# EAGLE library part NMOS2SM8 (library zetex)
Dual MOS FET
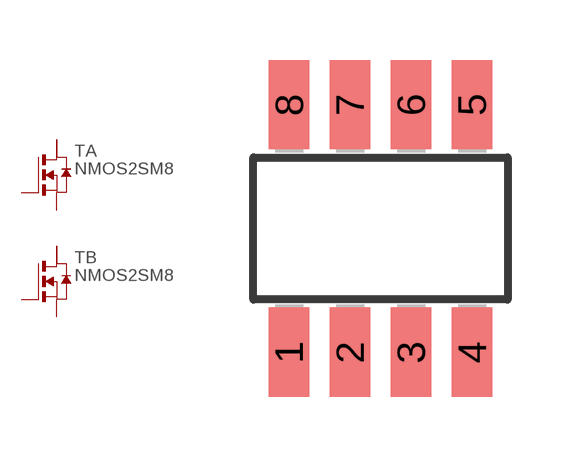
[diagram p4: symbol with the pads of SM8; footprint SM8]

Designator prefix T; gates A=N_MOS2D B=N_MOS2D

## NMOS2SM8 (OC_FARNELL: unknown; OC_NEWARK: unknown)  [SM8]
1  B:S  pas
2  B:G  pas
3  A:S  pas
4  A:G  pas
5  A:D  pas
6  A:D2  pas
7  B:D  pas
8  B:D2  pas

## Footprint SM8 (pad centres in mm)
SM8 Package
smd 1.016 x 2.235: 1 -2.286,-3.099; 2 -0.762,-3.099; 3 0.762,-3.099; 4 2.286,-3.099; 5 2.286,3.099; 6 0.762,3.099; 7 -0.762,3.099; 8 -2.286,3.099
